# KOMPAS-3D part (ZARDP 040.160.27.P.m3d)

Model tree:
1. Булева операция:23
2. Булева операция:24
3. Булева операция:25
4. Булева операция:26
5. Булева операция:27
6. Булева операция:28
7. Булева операция:29
8. Булева операция:30
9. Булева операция:31
10. Булева операция:32
11. Булева операция:33
12. Булева операция:34
13. Булева операция:35
14. Булева операция:36
15. Булева операция:37
16. Булева операция:38
17. Булева операция:39
18. Булева операция:40
19. Булева операция:41
20. Булева операция:42
21. Булева операция:43
22. Булева операция:44

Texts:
  ООО ИК Энерпред-Ярдос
